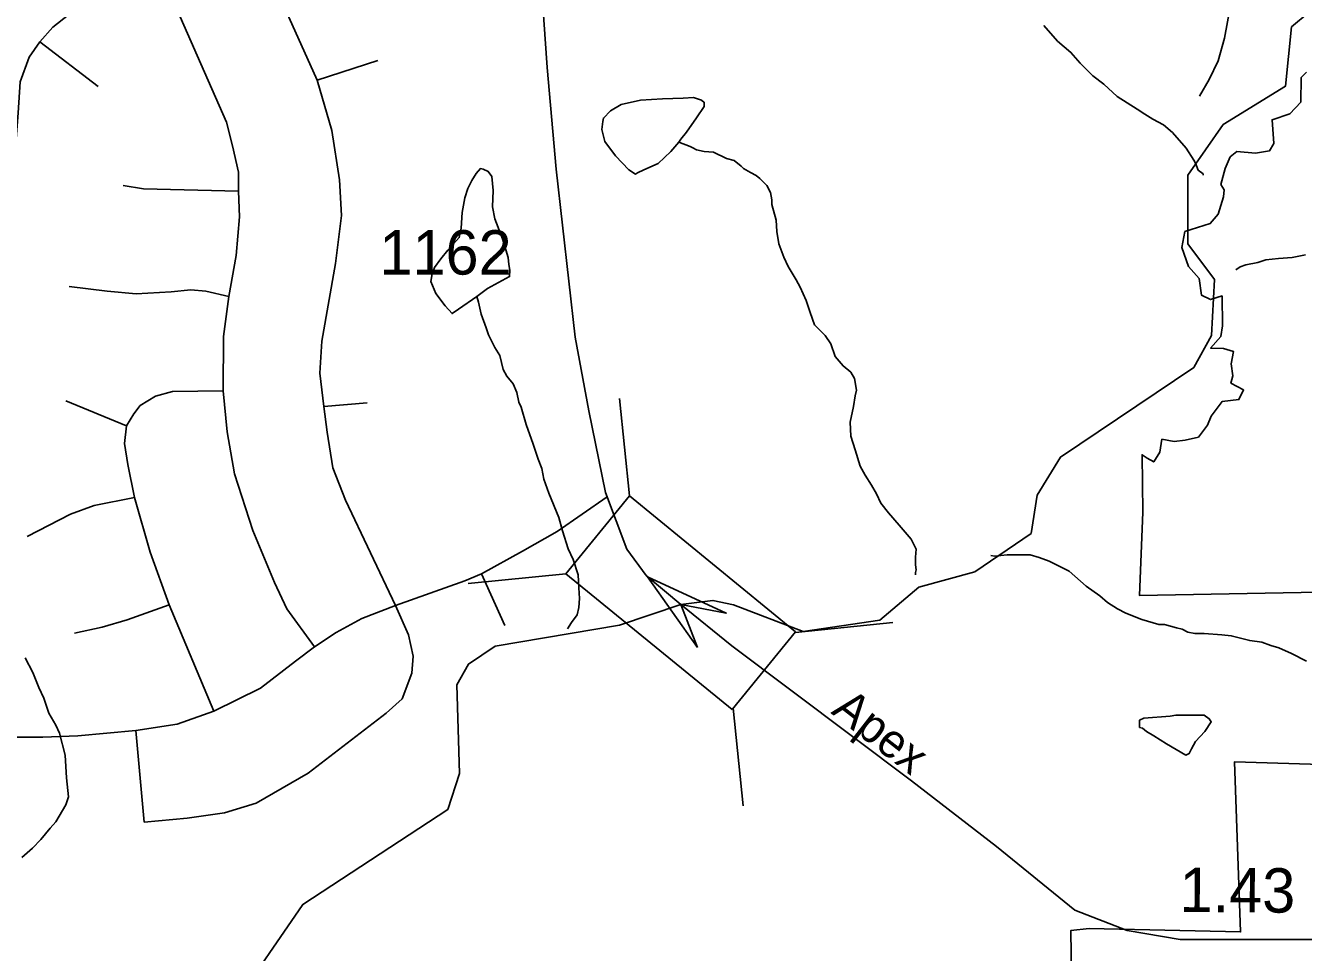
# Model space of a CAD drawing. Extents: x 2001466 to 2224147, y 644118 to 847247.
# Drawn here: x 2026475 to 2030071, y 717383 to 719991 of the extents above; entities that cross this region are included whole.
import ezdxf

# ---------------------------------------------------------------- set-up
doc = ezdxf.new("R2010")
doc.units = 0
for name, color, linetype in [('Exist Boundary Political City Limit New', 7, 'Continuous'), ('Exist Hydrographic Creek Single Shore', 7, 'Continuous'), ('Exist Hydrographic Misc Water Feature', 7, 'Continuous'), ('Exist Road Non-System Type 51', 7, 'Continuous'), ('Exist Road Secondary Mileage Hundredths English Label', 7, 'Continuous'), ('Exist Road Secondary Structure Standard Bridge Attributed CELL', 7, 'Continuous'), ('Exist Road Secondary Structure Standard Bridge CELL', 7, 'Continuous'), ('Exist Road Secondary Type 51 Attributed', 7, 'Continuous'), ('Exist Road Secondary Type 51 Label', 7, 'Continuous'), ('Exist Road Secondary Type 51 Number Label', 7, 'Continuous'), ('Map Preparation Boundary City Limit Buffer Line', 7, 'Continuous')]:
    doc.layers.add(name, color=color, linetype=linetype)

msp = doc.modelspace()

# ---------------------------------------------------------------- linework, layer by layer
at = {"layer": 'Exist Boundary Political City Limit New'}
for points in [[(2030079.1, 719859.5), (2030064.1, 719844.9), (2030063.2, 719775.1), (2030031.9, 719742.8), (2029982.6, 719726.1), (2029987.5, 719659.3), (2029975.4, 719638.6), (2029935.6, 719632.1), (2029883.4, 719636.7), (2029864.2, 719621.6), (2029850, 719588.8), (2029838.2, 719543.5), (2029847.1, 719529), (2029845.9, 719509.2), (2029830.9, 719460.4), (2029808.5, 719433.9), (2029737.1, 719411.4), (2029728.8, 719366.1), (2029747.4, 719313.1), (2029777.1, 719279.6), (2029783.4, 719232.6), (2029809, 719219.8), (2029841.9, 719230.4), (2029842.9, 719146.4), (2029838, 719115.6), (2029809.5, 719083.4), (2029845.9, 719081.9), (2029873.4, 719073.9), (2029867.1, 719039.4), (2029871.5, 719004.9), (2029866.5, 718985.1), (2029902.2, 718965.8), (2029889.1, 718938.7), (2029841.8, 718932.9), (2029811.1, 718891.8), (2029800.6, 718866.4), (2029774.9, 718832.9), (2029737.6, 718824.6), (2029707.2, 718820.1), (2029672.4, 718826.9), (2029666.2, 718790.3), (2029649.2, 718763.1), (2029630.6, 718773.8), (2029616.4, 718783.4), (2029618.4, 718621.9), (2029609.1, 718387.2), (2030367.5, 718401.7)], [(2030426.5, 717902.5), (2029877, 717919.4), (2029893.8, 717440.2), (2029467.9, 717449.9), (2029415.8, 717444.4), (2029418.5, 717244.4), (2029040.2, 717249.9), (2029020.1, 716698.6), (2028982.5, 715755.2), (2028970.8, 714782.2), (2028968.6, 714597.2), (2028966.4, 714449.7), (2029398.4, 714351.2), (2029776.1, 714265), (2030000, 714214.1), (2030233.2, 714161.1)]]:
    msp.add_lwpolyline(points, dxfattribs=at)
at = {"layer": 'Exist Hydrographic Creek Single Shore'}
msp.add_lwpolyline([(2027055.1, 717226.5), (2027255, 717517.7), (2027663.1, 717785), (2027696.1, 717886.1), (2027688.1, 718135.6), (2027721.1, 718194), (2027796.1, 718244.9), (2028146, 718303.4), (2028319, 718362), (2028408.8, 718373.1), (2028467.2, 718361.3), (2028663.1, 718286.3), (2028879, 718318), (2028988.1, 718410.9), (2029146, 718453.6), (2029304.1, 718562), (2029321.1, 718669.9), (2029387.1, 718776.8), (2029762, 719028.4), (2029812, 719119.2), (2029820, 719276.6), (2029745.2, 719376.5), (2029745.2, 719570.2), (2029845, 719712.5), (2030020.1, 719820.5), (2030037.2, 719987.4), (2030186, 720112.3)], dxfattribs=at)
at = {"layer": 'Exist Hydrographic Misc Water Feature'}
msp.add_line((2029788.6, 719569.8), (2029788.6, 719573.8), dxfattribs=at)
for points in [[(2029340.4, 719991.5), (2029378.5, 719947.6), (2029416.5, 719915.6), (2029442.5, 719885.6), (2029478.4, 719849.6), (2029508.5, 719825.7), (2029546.5, 719791.6), (2029602.7, 719755.7), (2029624.4, 719741.8), (2029646.5, 719727.7), (2029676.5, 719711.7), (2029702.5, 719689.8), (2029740.7, 719645.8), (2029762.6, 719611.8), (2029766.5, 719603.8), (2029774.5, 719583.8), (2029788.6, 719573.8)], [(2028312.7, 719663), (2028290.7, 719637), (2028254.8, 719602.9), (2028214.9, 719584.9), (2028196.8, 719576.9), (2028190.9, 719572.9), (2028172.8, 719584.9), (2028134.9, 719624.9), (2028104.7, 719664.8), (2028096.7, 719698.8), (2028098.8, 719720.9), (2028100.6, 719730.9), (2028120.7, 719750.9), (2028150.7, 719768.9), (2028204.8, 719780.8), (2028266.7, 719784.9), (2028324.8, 719786.9), (2028354.7, 719788.9), (2028376.6, 719781), (2028384.6, 719775), (2028384.6, 719763), (2028362.7, 719731), (2028334.6, 719690.9), (2028318.6, 719671), (2028312.7, 719663)], [(2028312.7, 719663), (2028344.7, 719651), (2028352.7, 719647), (2028362.7, 719641), (2028384.6, 719637), (2028410.7, 719635), (2028446.8, 719617.1), (2028468.7, 719611.1), (2028488.6, 719595.1), (2028494.8, 719589.1), (2028514.8, 719577.1), (2028530.6, 719569.1), (2028540.7, 719561.1), (2028560.8, 719541.1), (2028570.8, 719521.1), (2028574.7, 719501.1), (2028574.7, 719487.1), (2028586.8, 719443.2), (2028588.9, 719411.2), (2028594.8, 719377.2), (2028608.8, 719339.2), (2028620.9, 719313.2), (2028643, 719275.2), (2028654.9, 719255.2), (2028670.9, 719217.3), (2028683, 719183.2), (2028694.9, 719149.2), (2028725, 719119.3), (2028741, 719095.3), (2028752.9, 719059.3), (2028775.1, 719033.3), (2028797, 719015.4), (2028807, 718997.4), (2028813, 718965.4), (2028809.1, 718949.4), (2028805, 718919.3), (2028794.9, 718875.4), (2028797, 718835.4), (2028809.1, 718797.4), (2028823.2, 718751.4), (2028837.2, 718725.4), (2028855.2, 718697.4), (2028869.2, 718673.4), (2028881.1, 718647.4), (2028903.2, 718619.4), (2028933.4, 718585.5), (2028967.2, 718545.5), (2028981.3, 718517.5), (2028979.3, 718495.5), (2028979.3, 718473.5), (2028981.3, 718459.5), (2028979.3, 718451.5), (2028979.3, 718445.5)], [(2027745.1, 719228.7), (2027693, 719192.7), (2027675.2, 719180.7), (2027655.1, 719202.7), (2027629, 719236.6), (2027615.1, 719270.6), (2027619, 719292.6), (2027625.1, 719310.6), (2027643.2, 719334.6), (2027663.1, 719358.6), (2027695.1, 719394.6), (2027701, 719420.6), (2027703, 719464.6), (2027711, 719506.6), (2027719, 719532.6), (2027730.9, 719554.6), (2027742.8, 719574.6), (2027754.9, 719588.6), (2027762.9, 719586.6), (2027776.9, 719580.7), (2027786.9, 719566.7), (2027791, 719526.7), (2027789, 719480.7), (2027794.9, 719446.7), (2027816.9, 719390.7), (2027832.8, 719338.8), (2027835.1, 719318.7), (2027837.2, 719302.7), (2027836.9, 719284.7), (2027775, 719250.7), (2027745.1, 719228.7)], [(2029880.7, 719303.9), (2029892.6, 719311.9), (2029908.6, 719317.9), (2029942.6, 719323.9), (2029964.8, 719331.9), (2030000.7, 719336), (2030038.6, 719338), (2030076.7, 719346)], [(2027745.1, 719228.7), (2027749, 719212.6), (2027757, 719178.7), (2027771.1, 719140.7), (2027777.1, 719120.7), (2027795.1, 719084.7), (2027809.3, 719062.8), (2027819.1, 719022.7), (2027829.2, 719004.7), (2027847.2, 718982.8), (2027857.2, 718958.8), (2027863.2, 718930.8), (2027869.1, 718916.8), (2027883.1, 718868.8), (2027903.4, 718812.8), (2027917.3, 718770.9), (2027927.4, 718744.9), (2027933.3, 718714.9), (2027947.3, 718674.8), (2027975.4, 718606.9), (2027985.4, 718568.9), (2028001.4, 718518.9), (2028015.3, 718488.9), (2028029.5, 718445), (2028031.3, 718409), (2028033.4, 718379), (2028031.5, 718353), (2028027.4, 718333), (2028011.4, 718311), (2027999.6, 718293)], [(2029191.3, 718499.6), (2029201.4, 718497.6), (2029237.2, 718501.7), (2029279.3, 718501.7), (2029301.2, 718501.7), (2029327.3, 718493.7), (2029355.4, 718483.7), (2029411.3, 718455.7), (2029459.3, 718413.8), (2029497.3, 718385.8), (2029519.2, 718367.8), (2029547.3, 718349.9), (2029571.3, 718337.9), (2029615.4, 718319.9), (2029663.3, 718306), (2029679.3, 718306), (2029713.4, 718296), (2029729.4, 718292), (2029745.4, 718284), (2029765.3, 718280), (2029791.3, 718280), (2029841.3, 718276.1), (2029867.4, 718274.1), (2029919.3, 718260.1), (2029953.3, 718256.1), (2029979.3, 718246.1), (2030001.3, 718240.1), (2030037.4, 718224.1), (2030079.2, 718202.2)], [(2026464.1, 717650.2), (2026494.1, 717676.1), (2026518.1, 717700.1), (2026544.1, 717732.2), (2026560.1, 717750.2), (2026588, 717798.1), (2026596, 717820.2), (2026589.8, 717874.2), (2026585.9, 717938.1), (2026569.9, 718000.1), (2026559.9, 718022.2), (2026540, 718056.2), (2026533.8, 718076.1), (2026525.8, 718098.1), (2026511.9, 718128.1), (2026495.7, 718170.1), (2026473.8, 718212)], [(2029711.3, 718050), (2029791.3, 718050.1), (2029805.4, 718040.1), (2029811.4, 718032.1), (2029793.3, 718004.1), (2029767.3, 717976), (2029755.4, 717956), (2029749.5, 717942.1), (2029739.4, 717938.1), (2029685.5, 717970), (2029649.4, 717992), (2029629.3, 718004), (2029617.4, 718014), (2029609.4, 718016), (2029609.4, 718036), (2029621.3, 718042), (2029695.3, 718048), (2029711.3, 718050)]]:
    msp.add_lwpolyline(points, dxfattribs=at)
at = {"layer": 'Exist Road Non-System Type 51'}
for points in [[(2026514.7, 719945.1), (2026551.7, 719986.2), (2026596.1, 720021.4), (2026672, 720067.3), (2026858.7, 720133.6)], [(2026858.7, 720133.6), (2027040.3, 719719.2), (2027056.9, 719652.5), (2027073.6, 719578.4), (2027073.6, 719524.7)], [(2027173.4, 720109.6), (2027295.5, 719837.1)], [(2029863.8, 720037.1), (2029848.3, 719955.9), (2029830.8, 719891.8), (2029805.6, 719839.4), (2029778.4, 719792.7)], [(2026359.2, 719384.2), (2026418.5, 719534.2), (2026444.4, 719623.1), (2026453.6, 719745.5), (2026459.2, 719832.5), (2026485.1, 719902.5), (2026514.7, 719945.1)], [(2026514.7, 719945.1), (2026679.4, 719819.5)], [(2027295.5, 719837.1), (2027465.8, 719892.7)], [(2027295.5, 719837.1), (2027336.2, 719695.7), (2027358.4, 719556.8), (2027364, 719456.8), (2027347.3, 719321.4), (2027308.5, 719102.9), (2027302.9, 719013), (2027314, 718918.6)], [(2027073.6, 719524.7), (2026807.1, 719531.9), (2026749.7, 719541.2)], [(2027073.6, 719524.7), (2027076.6, 719452.9), (2027067.3, 719343.6), (2027047, 719228.8)], [(2027047, 719228.8), (2026982.2, 719243.6), (2026939.6, 719247.3), (2026884.1, 719241.7), (2026786, 719236.2), (2026704.6, 719243.6), (2026597.2, 719256.6)], [(2027047, 719228.8), (2027032.1, 719115.6), (2027030.8, 718962.8)], [(2027030.8, 718962.8), (2026888.3, 718961), (2026840.2, 718948), (2026797.7, 718922.1), (2026779.2, 718898), (2026758.8, 718864.7)], [(2027288.1, 718242.4), (2027210.4, 718349.9), (2027175.2, 718423.9), (2027114.1, 718570.2), (2027062.3, 718729.5), (2027042, 718848), (2027030.8, 718962.8)], [(2026758.8, 718864.7), (2026588.5, 718935.1)], [(2027314, 718918.6), (2027436.1, 718929.7)], [(2027314, 718918.6), (2027323.3, 718846.4), (2027339.9, 718746.4), (2027375.1, 718655.4), (2027515.7, 718359.1)], [(2026758.8, 718864.7), (2026753.2, 718814.7), (2026762.5, 718755.4), (2026781, 718662.8)], [(2026781, 718662.8), (2026668.1, 718640.6), (2026601.5, 718616.5), (2026479.3, 718553.6)], [(2026781, 718662.8), (2026825.4, 718509.1), (2026879.1, 718361)], [(2027758, 718448.6), (2027873.4, 718512), (2027970.7, 718567.5), (2028111, 718664.6)], [(2027515.7, 718359.1), (2027710.5, 718428.2), (2027758, 718448.6)], [(2027758, 718448.6), (2027823.6, 718302.6)], [(2026879.1, 718361), (2026760.7, 718318.4), (2026690.3, 718298), (2026612.6, 718281.3)], [(2027515.7, 718359.1), (2027552.7, 718276.2), (2027565.7, 718216.9), (2027562, 718168.7), (2027534.2, 718096.5), (2027489.8, 718055.8), (2027269.6, 717887.3), (2027123.4, 717803.2), (2027034.6, 717775.4), (2026929.1, 717760.6), (2026808.8, 717749.5)], [(2026879.1, 718361), (2027004.9, 718061.3)], [(2027515.7, 718359.1), (2027421.3, 718322.1), (2027349.2, 718283.2), (2027288.1, 718242.4)], [(2027004.9, 718061.3), (2027136.3, 718126.1), (2027234.4, 718202.1), (2027288.1, 718242.4)], [(2026784.7, 718006.9), (2026621.8, 717992.1), (2026523.8, 717988.4), (2026420.1, 717988.4), (2026336.8, 718005), (2026177.9, 718043.9), (2026057.6, 718058.7)], [(2026784.7, 718006.9), (2026901.3, 718025.4), (2027004.9, 718061.3)], [(2026808.8, 717749.5), (2026784.7, 718006.9)]]:
    msp.add_lwpolyline(points, dxfattribs=at)
at = {"layer": 'Exist Road Secondary Structure Standard Bridge Attributed CELL'}
msp.add_lwpolyline([(2028366, 718240.8), (2028225.2, 718439.9), (2028446.7, 718337.9), (2028319, 718362)], close=True, dxfattribs=at)
at = {"layer": 'Exist Road Secondary Structure Standard Bridge CELL'}
for p, q in [((2028146.2, 718941.8), (2028173.8, 718667.2)), ((2027720.4, 718421.1), (2027995, 718448.6)), ((2028640.9, 718283.5), (2028915.5, 718311.1)), ((2028466.1, 718069.9), (2028493.7, 717795.3))]:
    msp.add_line(p, q, dxfattribs=at)
msp.add_lwpolyline([(2028173.8, 718667.2), (2028641.7, 718284.5), (2028462.9, 718066), (2027995, 718448.6)], close=True, dxfattribs=at)
at = {"layer": 'Exist Road Secondary Type 51 Attributed'}
for points in [[(2028319, 718362), (2028221.3, 718443.4), (2028167, 718517.4), (2028106.3, 718677.1), (2028060.1, 718907), (2028021.8, 719114.5), (2027968.3, 719587.1), (2027942.8, 719872.9), (2027921.3, 720182.6), (2027929.2, 720438.1), (2027927.9, 720575.2), (2027925.6, 720637.6)], [(2033041.9, 717616.1), (2032858.4, 717573.8), (2032761.1, 717565.8), (2032641.4, 717591.4), (2032507.4, 717623.3), (2032344.7, 717652.1), (2032166, 717677.6), (2032060.7, 717677.6), (2031974.5, 717664.8), (2031830.9, 717601), (2031677.8, 717518), (2031505.5, 717457.3), (2031339.5, 717415.8), (2031071.5, 717406.2), (2030448.5, 717419), (2029724.1, 717419), (2029574.2, 717444.5), (2029427.4, 717502), (2029207.2, 717680.8), (2028967.9, 717866), (2028462.6, 718245.8), (2028319, 718362)]]:
    msp.add_lwpolyline(points, dxfattribs=at)
at = {"layer": 'Map Preparation Boundary City Limit Buffer Line'}
for points in [[(2030079.1, 719859.5), (2030064.1, 719844.9), (2030063.2, 719775.1), (2030031.9, 719742.8), (2029982.6, 719726.1), (2029987.5, 719659.3), (2029975.4, 719638.6), (2029935.6, 719632.1), (2029883.4, 719636.7), (2029864.2, 719621.6), (2029850, 719588.8), (2029838.2, 719543.5), (2029847.1, 719529), (2029845.9, 719509.2), (2029830.9, 719460.4), (2029808.5, 719433.9), (2029737.1, 719411.4), (2029728.8, 719366.1), (2029747.4, 719313.1), (2029777.1, 719279.6), (2029783.4, 719232.6), (2029809, 719219.8), (2029841.9, 719230.4), (2029842.9, 719146.4), (2029838, 719115.6), (2029809.5, 719083.4), (2029845.9, 719081.9), (2029873.4, 719073.9), (2029867.1, 719039.4), (2029871.5, 719004.9), (2029866.5, 718985.1), (2029902.2, 718965.8), (2029889.1, 718938.7), (2029841.8, 718932.9), (2029811.1, 718891.8), (2029800.6, 718866.4), (2029774.9, 718832.9), (2029737.6, 718824.6), (2029707.2, 718820.1), (2029672.4, 718826.9), (2029666.2, 718790.3), (2029649.2, 718763.1), (2029630.6, 718773.8), (2029616.4, 718783.4), (2029618.4, 718621.9), (2029609.1, 718387.2), (2030367.5, 718401.7)], [(2030426.5, 717902.5), (2029877, 717919.4), (2029893.8, 717440.2), (2029467.9, 717449.9), (2029415.8, 717444.4), (2029418.5, 717244.4), (2029040.2, 717249.9), (2029020.1, 716698.6), (2028982.5, 715755.2), (2028970.8, 714782.2), (2028968.6, 714597.2), (2028966.4, 714449.7), (2029398.4, 714351.2), (2029776.1, 714265), (2030000, 714214.1), (2030233.2, 714161.1)]]:
    msp.add_lwpolyline(points, dxfattribs=at)

# ---------------------------------------------------------------- texts
at = {"layer": 'Exist Road Secondary Mileage Hundredths English Label'}
msp.add_text('1.43', height=125, rotation=359.585, dxfattribs=at).set_placement((2029721.9, 717496.7))
at = {"layer": 'Exist Road Secondary Type 51 Label'}
msp.add_text('Apex', height=95, rotation=322.0299, dxfattribs=at).set_placement((2028738.8, 718056.9))
at = {"layer": 'Exist Road Secondary Type 51 Number Label'}
msp.add_text('1162', height=125, dxfattribs=at).set_placement((2027470.6, 719290.3))

doc.saveas('drawing.dxf')
